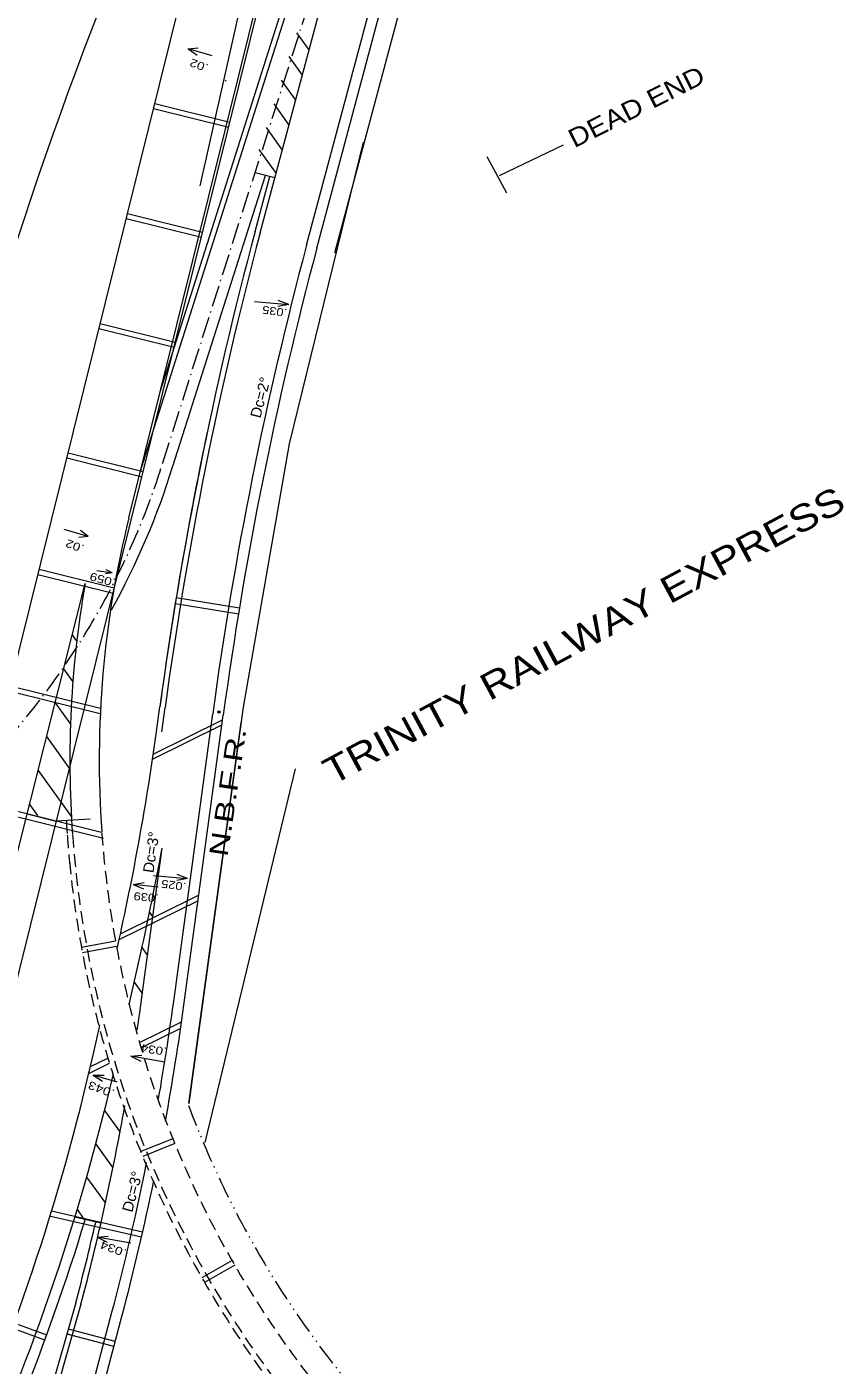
# Model space of a CAD drawing. Extents: x 2354993 to 2372084, y 6966390 to 6990057.
# Drawn here: x 2364793 to 2365387, y 6978638 to 6979642 of the extents above; entities that cross this region are included whole.
import ezdxf

# ---------------------------------------------------------------- set-up
doc = ezdxf.new("R2010")
doc.units = 0
doc.header["$LTSCALE"] = 3.2
doc.header["$PDMODE"] = 32
doc.header["$PDSIZE"] = 1.6
for name, pattern in [('DASH_DOUBLE_DOT', [9.2, 5, -1.2, 0.3, -1.2, 0.3, -1.2]), ('DOT_DASHED', [7.7, 5, -1.2, 0.3, -1.2]), ('MEDIUM_DASHED', [4.5, 3, -1.5])]:
    doc.linetypes.add(name, pattern=pattern)
for name, color, linetype, lineweight in [('10', 7, 'Continuous', 13), ('12', 7, 'Continuous', 13), ('13', 7, 'Continuous', 13), ('17', 7, 'Continuous', 13), ('19', 7, 'Continuous', 13), ('23', 7, 'Continuous', 13), ('5', 7, 'Continuous', 13), ('6', 7, 'Continuous', 13), ('60', 7, 'DASH_DOUBLE_DOT', 13), ('61', 7, 'Continuous', 13), ('7', 7, 'Continuous', 13), ('9', 7, 'Continuous', 13)]:
    doc.layers.add(name, color=color, linetype=linetype, lineweight=lineweight)

msp = doc.modelspace()

# ---------------------------------------------------------------- linework, layer by layer
at = {"layer": '10'}
for p, q in [((2364872.432, 6978998.843), (2364880.627, 6979000.217)), ((2364842.306, 6978855.831), (2364850.616, 6978855.763))]:
    msp.add_line(p, q, dxfattribs=at)
for points in [[(2364891.069, 6978996.771), (2364872.432, 6978998.843), (2364880.128, 6978995.698)], [(2364860.3, 6978850.558), (2364842.306, 6978855.831), (2364849.337, 6978851.4)]]:
    msp.add_lwpolyline(points, dxfattribs=at)
at = {"layer": '12'}
for p, q in [((2364886.848, 6979092.839), (2364938.873, 6979118.544)), ((2364887.391, 6979096.536), (2364939.356, 6979122.209)), ((2364861.836, 6978957.555), (2364921.28, 6978986.925)), ((2364862.795, 6978961.889), (2364921.229, 6978990.76)), ((2364877.055, 6978880.34), (2364908.657, 6978895.953)), ((2364878.201, 6978876.445), (2364907.967, 6978891.151)), ((2364838.628, 6978856.893), (2364854.562, 6978864.765)), ((2364840.451, 6978862.255), (2364853.394, 6978868.65)), ((2364806.102, 6978657.217), (2364781.694, 6978666.176)), ((2364807.48, 6978660.972), (2364783.072, 6978669.931))]:
    msp.add_line(p, q, dxfattribs=at)
at = {"layer": '13'}
msp.add_line((2364922.585, 6979522.917), (2365036.612, 6980031.444), dxfattribs=at)
at = {"layer": '17'}
for p, q in [((2364913.656, 6979625.58), (2364921.106, 6979626.249)), ((2364838.514, 6979259.789), (2364820.521, 6979265.065)), ((2364838.514, 6979259.789), (2364831.573, 6979258.986)), ((2364838.514, 6979259.789), (2364832.75, 6979264.248)), ((2364856.678, 6979232.519), (2364851.515, 6979231.94)), ((2364902.082, 6978808.216), (2364878.186, 6978798.547)), ((2364903.582, 6978804.508), (2364879.687, 6978794.839)), ((2364879.454, 6978738.16), (2364811.117, 6978753.77)), ((2364878.563, 6978734.26), (2364810.226, 6978749.871)), ((2364946.472, 6978716.745), (2364923.897, 6978703.846)), ((2364948.456, 6978713.272), (2364925.882, 6978700.373)), ((2364858.944, 6978656.195), (2364823.785, 6978665.465)), ((2364857.924, 6978652.327), (2364822.766, 6978661.597))]:
    msp.add_line(p, q, dxfattribs=at)
for points in [[(2364931.647, 6979620.306), (2364913.654, 6979625.582), (2364920.211, 6979620.689)], [(2364845.118, 6979234.449), (2364856.678, 6979232.519), (2364851.986, 6979234.747)]]:
    msp.add_lwpolyline(points, dxfattribs=at)
at = {"layer": '19'}
for p, q in [((2364988.942, 6979433.834), (2364980.787, 6979432.231)), ((2364913.187, 6979003.359), (2364905.032, 6979001.756)), ((2364870.598, 6978870.07), (2364878.081, 6978866.449)), ((2364845.231, 6978734.341), (2364852.714, 6978730.72))]:
    msp.add_line(p, q, dxfattribs=at)
for points in [[(2364963.249, 6979435.987), (2364988.942, 6979433.834), (2364981.172, 6979436.768)], [(2364887.494, 6979005.512), (2364913.187, 6979003.359), (2364905.417, 6979006.293)], [(2364896, 6978865.629), (2364870.598, 6978870.07), (2364878.86, 6978870.936)], [(2364870.633, 6978729.9), (2364845.231, 6978734.341), (2364853.493, 6978735.207)]]:
    msp.add_lwpolyline(points, dxfattribs=at)
at = {"layer": '23'}
for p, q in [((2365023.63, 6979472.53), (2365130.321, 6979872.599)), ((2364989.616, 6979329.308), (2365045.088, 6979555.624)), ((2364955.036, 6979131.858), (2364989.616, 6979329.308)), ((2364914.348, 6978834.604), (2364955.036, 6979131.858)), ((2364952.982, 6979120.351), (2364913.926, 6978834.661))]:
    msp.add_line(p, q, dxfattribs=at)
at = {"layer": '5'}
for p, q in [((2364760.631, 6978828.473), (2365077.413, 6980104.485)), ((2364952, 6979607.617), (2365075.472, 6980104.967)), ((2364704.339, 6978842.448), (2365012.522, 6980083.82)), ((2364967.588, 6979487.475), (2365074.28, 6979887.544)), ((2365002.373, 6979478.198), (2365109.064, 6979878.268)), ((2365010.102, 6979476.137), (2365116.794, 6979876.206)), ((2364967.588, 6979487.475), (2365045.124, 6979778.215)), ((2364994.9, 6979637.629), (2365004.181, 6979624.688)), ((2364989.168, 6979619.883), (2364999.177, 6979605.926)), ((2364869.155, 6979273.916), (2364952.974, 6979611.544)), ((2364942.18, 6979601.264), (2364941.597, 6979602.077)), ((2364983.436, 6979602.137), (2364994.174, 6979587.164)), ((2364977.704, 6979584.391), (2364989.17, 6979568.403)), ((2364971.972, 6979566.645), (2364984.167, 6979549.641)), ((2364966.622, 6979550.083), (2364979.497, 6979532.129)), ((2365152.455, 6979517.382), (2365137.889, 6979544.461)), ((2364902.17, 6979312.668), (2364971.472, 6979530.58)), ((2364963.723, 6979488.506), (2364974.713, 6979529.715)), ((2364978.578, 6979528.685), (2364963.733, 6979532.643)), ((2364775.353, 6978982.176), (2364836.312, 6979224.63)), ((2364826.593, 6979185.972), (2364830.037, 6979181.168)), ((2364820.204, 6979160.562), (2364827.134, 6979150.898)), ((2364813.815, 6979135.152), (2364825.362, 6979119.05)), ((2364889.798, 6979113.582), (2364892.323, 6979132.188)), ((2364893.796, 6979113.3), (2364896.287, 6979131.65)), ((2364902.457, 6978909.452), (2364931.96, 6979126.807)), ((2364910.384, 6978908.376), (2364939.887, 6979125.731)), ((2364807.426, 6979109.742), (2364824.911, 6979085.361)), ((2364993.883, 6979085.613), (2364926.071, 6978805.28)), ((2364801.038, 6979084.332), (2364826.035, 6979049.475)), ((2364794.649, 6979058.922), (2364800.642, 6979050.565)), ((2364792.853, 6979051.778), (2364814.704, 6979046.284)), ((2364840.154, 6979047.753), (2364814.704, 6979046.284)), ((2364878.675, 6978912.68), (2364894.066, 6979026.071)), ((2364884.647, 6978977.943), (2364887.074, 6978974.56)), ((2364869.322, 6978908.963), (2364878.037, 6978947.539)), ((2364878.945, 6978951.577), (2364883.157, 6978945.703)), ((2364873.052, 6978925.475), (2364879.24, 6978916.846)), ((2364878.675, 6978912.68), (2364879.038, 6978915.352)), ((2364842.776, 6978873.14), (2364847.262, 6978893)), ((2364850.842, 6978829.41), (2364862.47, 6978813.196)), ((2364844.297, 6978804.218), (2364857.15, 6978786.296)), ((2364837.453, 6978779.443), (2364851.52, 6978759.828)), ((2364830.32, 6978755.071), (2364835.642, 6978747.65)), ((2364848.144, 6978744.79), (2364828.648, 6978749.249)), ((2364829.342, 6978685.127), (2364801.736, 6978589.013)), ((2364833.209, 6978684.108), (2364805.681, 6978587.971)), ((2364797.288, 6978453.72), (2364856.416, 6978677.989)), ((2364805.021, 6978451.673), (2364864.153, 6978675.957))]:
    msp.add_line(p, q, dxfattribs=at)
for points in [[(2364881.181, 6979319.258), (2364881.205, 6979319.336), (2365034.333, 6979800.831), (2365034.325, 6979800.806)], [(2364892.613, 6979368.406), (2365030.521, 6979802.044), (2365030.511, 6979802.011)]]:
    msp.add_lwpolyline(points, dxfattribs=at)
for centre, radius, start, end in [((2367632.916, 6978563.811), 2992, 157.9609, 178.42915), ((2367758.826, 6978743.101), 2892.789, 165.06774, 172.27016), ((2367758.826, 6978743.101), 2888.789, 165.06774, 172.27016), ((2367758.826, 6978743.101), 2852.789, 165.06774, 172.27016), ((2367758.826, 6978743.101), 2844.789, 165.06774, 172.27016), ((2367758.826, 6978743.101), 2892.789, 168.1183, 172.27016), ((2364347.535, 6979485.558), 558.958, 341.57402, 342.6914), ((2364347.535, 6979485.558), 580.958, 331.09011, 342.6914), ((2365602.828, 6979091.775), 755.944, 166.05766, 184.04951), ((2365602.828, 6979091.775), 777.944, 170.16699, 184.0701), ((2363001.466, 6979371.469), 1905.859, 347.27016, 352.27016), ((2363001.466, 6979371.469), 1923.859, 347.27016, 349.65738), ((2362998.061, 6979167.946), 1897.859, 351.57279, 352.27016), ((2362998.061, 6979167.946), 1921.859, 350.12288, 352.27016), ((2362998.061, 6979167.946), 1929.859, 349.6518, 352.27016), ((2363217.727, 6979240.251), 1666, 323.74727, 347.27016), ((2363217.727, 6979240.251), 1684, 323.49687, 346.83945), ((2362998.061, 6979167.946), 1897.859, 345.23003, 349.82741), ((2362998.061, 6979167.946), 1921.859, 345.23003, 348.66846), ((2362998.061, 6979167.946), 1929.859, 345.23003, 348.30079), ((2363217.727, 6979240.251), 1692, 323.39108, 343.06808), ((2362998.061, 6979167.946), 1893.859, 345.23003, 347.11677)]:
    msp.add_arc(centre, radius, start, end, dxfattribs=at)
at = {"layer": '5', "linetype": 'MEDIUM_DASHED'}
for radius, start, end in [(781.944, 183.30348, 184.0701), (781.944, 184.10654, 185.65802), (777.944, 184.10654, 276.23324), (755.944, 184.10697, 276.23324), (781.944, 185.55228, 276.23324)]:
    msp.add_arc((2365602.828, 6979091.775), radius, start, end, dxfattribs=at)
at = {"layer": '6', "linetype": 'DOT_DASHED'}
msp.add_line((2364894.547, 6979315.093), (2365047.675, 6979796.588), dxfattribs=at)
msp.add_arc((2364347.535, 6979485.558), 572.958, 296.29328, 342.6914, dxfattribs=at)
at = {"layer": '60'}
msp.add_arc((2365602.828, 6979091.775), 735.944, 200.58365, 276.23324, dxfattribs=at)
at = {"layer": '61'}
for p, q in [((2364887.629, 6979580.746), (2364944.124, 6979566.72)), ((2364888.592, 6979584.628), (2364944.8, 6979570.674)), ((2364867.148, 6979498.25), (2364923.643, 6979484.225)), ((2364868.112, 6979502.132), (2364924.32, 6979488.178)), ((2364847.632, 6979419.636), (2364903.839, 6979405.682)), ((2364846.668, 6979415.754), (2364903.163, 6979401.729)), ((2364822.573, 6979318.7), (2364879.068, 6979304.675)), ((2364823.537, 6979322.582), (2364879.745, 6979308.628)), ((2364801.852, 6979235.234), (2364858.06, 6979221.28)), ((2364800.888, 6979231.352), (2364857.383, 6979217.326)), ((2364903.924, 6979209.67), (2364951.562, 6979201.925)), ((2364904.474, 6979214.146), (2364952.112, 6979206.401)), ((2364780.167, 6979147.886), (2364847.906, 6979131.069)), ((2364779.203, 6979144.003), (2364847.705, 6979126.997)), ((2364757.518, 6979056.655), (2364849.98, 6979033.7)), ((2364758.482, 6979060.537), (2364848.476, 6979038.195)), ((2364859.106, 6978956.334), (2364833.551, 6978951.54)), ((2364859.843, 6978952.402), (2364834.289, 6978947.609))]:
    msp.add_line(p, q, dxfattribs=at)
at = {"layer": '7'}
msp.add_line((2365194.839, 6979553.307), (2365146.764, 6979530.287), dxfattribs=at)
at = {"layer": '9'}
msp.add_arc((2360722.521, 6984327.136), 5729.573, 359.50797, 359.50797, dxfattribs=at)
msp.add_point((2364936.71, 6979128.233), dxfattribs=at)

# ---------------------------------------------------------------- texts
at = {"layer": '10'}
for s, rotation, width, p in [('.039', 174.81, 1.2, (2364891.665, 6978991.441)), ('.043', 159.81, 1.3, (2364858.988, 6978844.573))]:
    msp.add_text(s, height=6, rotation=rotation, dxfattribs=dict(at, width=width)).set_placement(p)
at = {"layer": '13'}
for s, height, rotation, width, p in [('TRINITY RAILWAY EXPRESS', 20, 28.245, 1.2, (2365021.709, 6979072.937)), ('N.B.F.R.', 14, 81.552, 1.35, (2364943.026, 6979019.149))]:
    msp.add_text(s, height=height, rotation=rotation, dxfattribs=dict(at, width=width)).set_placement(p)
at = {"layer": '17'}
for s, height, rotation, width, p in [('.02', 6, 159.81, 1.25, (2364929.282, 6979613.641)), ('Dc=2°', 8, 75.543, 1.05, (2364967.737, 6979348.071)), ('.02', 6, 159.81, 1.25, (2364836.149, 6979253.124)), ('.059', 6, 164.81, 1.25, (2364859.614, 6979227.898)), ('Dc=3°', 8, 75.543, 1.05, (2364871.66, 6978752.534))]:
    msp.add_text(s, height=height, rotation=rotation, dxfattribs=dict(at, width=width)).set_placement(p)
at = {"layer": '19'}
for s, rotation, width, p in [('.035', 171.703, 1.2, (2364988.165, 6979430.35)), ('.025', 171.703, 1.2, (2364912.41, 6978999.875)), ('.034', 171.703, 1.25, (2364897.897, 6978876.395)), ('.034', 159.703, 1.3, (2364868.002, 6978724.874))]:
    msp.add_text(s, height=6, rotation=rotation, dxfattribs=dict(at, width=width)).set_placement(p)
at = {"layer": '7'}
for s, height, rotation, width, p in [('DEAD END', 14, 26.686, 1.15, (2365203.148, 6979550.89)), ('Dc=3°', 8, 81.505, 1.05, (2364887.498, 6979007.121))]:
    msp.add_text(s, height=height, rotation=rotation, dxfattribs=dict(at, width=width)).set_placement(p)

doc.saveas('drawing.dxf')
